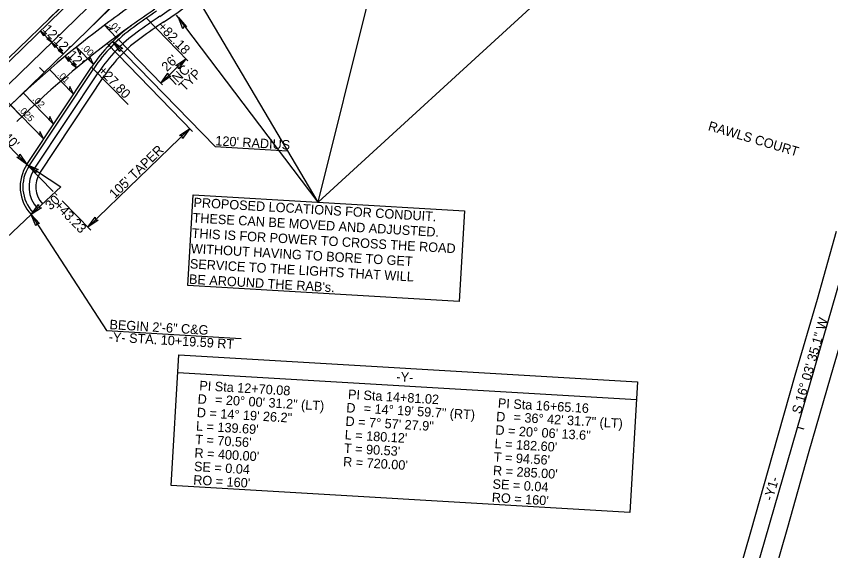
# Model space of a CAD drawing. Extents: x 2010838 to 2015151, y 441905 to 447792.
# Drawn here: x 2011692 to 2012294, y 444289 to 444685 of the extents above; entities that cross this region are included whole.
import ezdxf

# ---------------------------------------------------------------- set-up
doc = ezdxf.new("R2010")
doc.units = 0
for name, color, linetype in [('$AUDIT_BAD_LAYER1', 7, 'Continuous'), ('A-Wall-Blow', 7, 'Continuous'), ('A-Wall-Comp', 7, 'Continuous'), ('C-Building', 7, 'Continuous'), ('C-Grave Plots', 7, 'Continuous'), ('CLRD', 7, 'Continuous'), ('Cont-2-Lidar', 7, 'Continuous'), ('Default_2FT_LIDAR_Contour', 7, 'Continuous'), ('Default_Parcels', 7, 'Continuous'), ('HATCH', 7, 'Continuous'), ('s-Existing Major', 7, 'Continuous'), ('S-Existing Minor', 7, 'Continuous'), ('S-overhead electric', 7, 'Continuous'), ('TEXT-LG', 7, 'Continuous'), ('TEXT-MED', 7, 'Continuous'), ('X2', 7, 'Continuous')]:
    doc.layers.add(name, color=color, linetype=linetype)

msp = doc.modelspace()

# ---------------------------------------------------------------- linework, layer by layer
at = {"layer": '$AUDIT_BAD_LAYER1'}
msp.add_line((2012370.93, 444732.79), (2012193.35, 444115.92), dxfattribs=at)
at = {"layer": 'A-Wall-Blow'}
for p, q in [((2011756.93, 444678.31), (2011765.89, 444669.09)), ((2011736.32, 444662.22), (2011748.79, 444649.38)), ((2011716.32, 444645.49), (2011734.06, 444627.23)), ((2011670.73, 444636.45), (2011712, 444593.97)), ((2011696.78, 444628.3), (2011719.35, 444605.06)), ((2011687.45, 444619.24), (2011695.83, 444610.62))]:
    msp.add_line(p, q, dxfattribs=at)
at = {"layer": 'A-Wall-Comp'}
for points in [[(2011756.93, 444678.31), (2011762.55, 444675.4), (2011760.16, 444675)], [(2011736.32, 444662.22), (2011739.06, 444656.52), (2011739.54, 444658.9)], [(2011748.79, 444649.38), (2011746.04, 444655.08), (2011745.56, 444652.7)], [(2011734.06, 444627.23), (2011731.31, 444632.93), (2011730.84, 444630.55)], [(2011719.35, 444605.06), (2011716.61, 444610.75), (2011716.13, 444608.37)], [(2011712, 444593.97), (2011709.25, 444599.67), (2011708.77, 444597.29)]]:
    msp.add_lwpolyline(points, close=True, dxfattribs=at)
at = {"layer": 'C-Building'}
for p, q in [((2011712.43, 444643.5), (2011708.94, 444647.09)), ((2012269.58, 444380.73), (2012274.38, 444379.35))]:
    msp.add_line(p, q, dxfattribs=at)
at = {"layer": 'CLRD'}
for p, q in [((2012370.93, 444732.79), (2012193.35, 444115.92)), ((2011353.78, 444295.11), (2011783.81, 444712.84))]:
    msp.add_line(p, q, dxfattribs=at)
at = {"layer": 'Default_Parcels'}
msp.add_line((2011811.22, 444421.15), (2012150.63, 444401.14), dxfattribs=at)
msp.add_lwpolyline([(2011811.99, 444434.1), (2012151.4, 444414.1), (2012145.7, 444317.47), (2011806.29, 444337.48)], close=True, dxfattribs=at)
at = {"layer": 'HATCH'}
msp.add_line((2011772.09, 444718.19), (2011632.34, 444582.43), dxfattribs=at)
msp.add_arc((2012222.81, 444060.23), 762, 125.84212, 134.15261, dxfattribs=at)
at = {"layer": 's-Existing Major'}
for points in [[(2011814.82, 444675.57), (2011811.68, 444684.14), (2011817.57, 444677.1), (2011815.61, 444677.3)], [(2011712.2, 444670.46), (2011709.62, 444674.23), (2011713.34, 444671.54), (2011712.37, 444671.4)], [(2011715.4, 444669.39), (2011717.98, 444665.62), (2011714.25, 444668.31), (2011715.23, 444668.45)], [(2011720.56, 444661.85), (2011717.98, 444665.62), (2011721.71, 444662.93), (2011720.73, 444662.79)], [(2011768.26, 444658.88), (2011763.1, 444666.42), (2011770.55, 444661.04), (2011768.6, 444660.75)], [(2011723.76, 444660.78), (2011726.34, 444657.01), (2011722.61, 444659.7), (2011723.59, 444659.85)], [(2011730.53, 444651.59), (2011727.95, 444655.36), (2011731.67, 444652.67), (2011730.7, 444652.53)], [(2011733.73, 444650.52), (2011736.31, 444646.75), (2011732.58, 444649.44), (2011733.56, 444649.59)], [(2011809.68, 444648.41), (2011817.22, 444653.57), (2011811.84, 444646.12), (2011811.55, 444648.07)], [(2011806.05, 444640.69), (2011798.57, 444635.45), (2011803.86, 444642.96), (2011804.17, 444641.02)], [(2011812.51, 444596.78), (2011820.04, 444601.94), (2011814.67, 444594.48), (2011814.38, 444596.43)], [(2011694.42, 444582.79), (2011699.58, 444575.25), (2011692.13, 444580.63), (2011694.07, 444580.92)], [(2011706.21, 444568.97), (2011699.57, 444575.24), (2011707.99, 444571.57), (2011706.15, 444570.87)], [(2011710.32, 444543.15), (2011702.69, 444538.12), (2011708.2, 444545.48), (2011708.45, 444543.53)], [(2011706.28, 444529.73), (2011702.69, 444538.12), (2011708.96, 444531.4), (2011706.99, 444531.49)], [(2011752.26, 444533.94), (2011744.73, 444528.78), (2011750.1, 444536.23), (2011750.39, 444534.28)]]:
    msp.add_lwpolyline(points, close=True, dxfattribs=at)
at = {"layer": 'S-Existing Minor'}
for p, q in [((2011915.11, 444547.35), (2012067.43, 445160.54)), ((2011915.11, 444547.35), (2011665.38, 444969.67)), ((2011915.11, 444547.35), (2012331.51, 444929.43)), ((2011915.11, 444547.35), (2011810.36, 444685.84)), ((2011788.05, 444683.59), (2011818.69, 444652.05)), ((2011709.62, 444674.23), (2011726.34, 444657.01)), ((2011766.77, 444668.19), (2011799.86, 444634.12)), ((2011758.98, 444664.8), (2011822.18, 444599.74)), ((2011763.1, 444666.42), (2011838.76, 444588.53)), ((2011736.33, 444646.73), (2011727.95, 444655.36)), ((2011798.57, 444635.45), (2011817.22, 444653.57)), ((2011747.43, 444647.38), (2011774.41, 444619.59)), ((2011671.71, 444603.94), (2011699.58, 444575.25)), ((2011744.73, 444528.78), (2011820.04, 444601.94)), ((2011838.76, 444588.53), (2011892.29, 444585.38)), ((2011699.57, 444575.24), (2011724.57, 444558.65)), ((2011699.58, 444575.25), (2011719.11, 444555.15)), ((2011702.69, 444538.12), (2011724.57, 444558.65)), ((2011725.75, 444548.31), (2011746.86, 444526.58)), ((2011702.69, 444538.12), (2011758.35, 444452.21)), ((2011758.35, 444452.21), (2011858.18, 444446.32))]:
    msp.add_line(p, q, dxfattribs=at)
msp.add_lwpolyline([(2011822.62, 444552.8), (2012023.4, 444540.96), (2012019.43, 444473.76), (2011818.65, 444485.59)], close=True, dxfattribs=at)
at = {"layer": 'S-overhead electric'}
for p, q in [((2011623.98, 444591.04), (2011755.87, 444719.16)), ((2011699.57, 444575.24), (2011747.43, 444647.38)), ((2011702.69, 444538.12), (2011684.45, 444521))]:
    msp.add_line(p, q, dxfattribs=at)
for points in [[(2012214.85, 444140.57), (2012231.36, 444197.54), (2012246.95, 444252.5), (2012262.48, 444306.6), (2012277.82, 444361.05), (2012294.5, 444419.12), (2012308.07, 444465.48), (2012323.92, 444521.61), (2012337.25, 444572.21), (2012352.19, 444622.1), (2012368.35, 444674.41)], [(2012298.31, 444525.62), (2012284.21, 444475.17), (2012267.75, 444418.87), (2012251.33, 444361.5), (2012234.87, 444302.97), (2012222.75, 444260.78), (2012211.14, 444219.75), (2012193.27, 444158.36)]]:
    msp.add_lwpolyline(points, dxfattribs=at)
for centre, radius, start, end in [((2011328.64, 445107.17), 600, 314.56735, 343.62875), ((2012222.81, 444060.23), 774, 124.04743, 127.31977), ((2012222.81, 444060.23), 762, 124.2188, 125.78328), ((2011328.64, 445107.17), 600, 314.16903, 314.56735), ((2012222.81, 444060.23), 774, 127.31977, 134.16903), ((2011847.42, 444581.04), 120, 125.78328, 146.4397), ((2011724.57, 444558.65), 30, 146.4397, 223.18139)]:
    msp.add_arc(centre, radius, start, end, dxfattribs=at)
at = {"layer": 'TEXT-LG'}
for p, q in [((2011704.98, 444571.64), (2011752.84, 444643.78)), ((2011709.15, 444568.88), (2011757.01, 444641.02))]:
    msp.add_line(p, q, dxfattribs=at)
for centre, radius, start, end in [((2011629.97, 444941.31), 306.5, 303.21306, 341.32797), ((2011629.97, 444941.31), 311.5, 303.21306, 341.32797), ((2012222.81, 444060.23), 755.5, 124.2188, 125.78328), ((2012222.81, 444060.23), 750.5, 124.2188, 125.78328), ((2011847.42, 444581.04), 113.5, 125.78328, 146.4397), ((2011847.42, 444581.04), 108.5, 125.78328, 146.4397), ((2011724.57, 444558.65), 23.5, 146.4397, 223.18139), ((2011724.57, 444558.65), 18.5, 146.4397, 223.18139)]:
    msp.add_arc(centre, radius, start, end, dxfattribs=at)
at = {"layer": 'TEXT-MED'}
for p, q in [((2011651.27, 444620.34), (2011754.48, 444720.6)), ((2011701.23, 444574.13), (2011749.09, 444646.27))]:
    msp.add_line(p, q, dxfattribs=at)
for centre, radius, start, end in [((2012222.81, 444060.23), 760, 124.2188, 125.78328), ((2011847.42, 444581.04), 118, 125.78328, 146.4397), ((2011724.57, 444558.65), 28, 146.4397, 223.18139)]:
    msp.add_arc(centre, radius, start, end, dxfattribs=at)
at = {"layer": 'X2'}
for p, q in [((2011715.81, 444683.04), (2011730.15, 444696.97)), ((2011678.66, 444646.95), (2011693, 444660.88))]:
    msp.add_line(p, q, dxfattribs=at)

# ---------------------------------------------------------------- texts
at = {"layer": 'A-Wall-Blow'}
for s, p in [('.01', (2011759.99, 444678.67)), ('.00', (2011739.48, 444661.69)), ('.01', (2011721.66, 444641.45)), ('.02', (2011703.31, 444623.23)), ('.025', (2011692.83, 444615.74))]:
    msp.add_text(s, height=5, rotation=314.16903, dxfattribs=at).set_placement(p)
at = {"layer": 'C-Grave Plots'}
for s, rotation, p in [("12'", 314.16903, (2011710.68, 444674.92)), ('+82.18', 314.16436, (2011795.86, 444676.86)), ("12'", 314.16903, (2011718.94, 444666.24)), ("12'", 314.16903, (2011729.12, 444655.67)), ("26'", 44.07451, (2011803.2, 444643.62)), ('+27.80', 314.16436, (2011751.78, 444644.17)), ('INC. ', 44.07451, (2011809.14, 444633.54)), ('TYP', 44.07451, (2011816.05, 444628.95)), ('RAWLS COURT', 343.5592, (2012203.02, 444600.72)), ("40'", 314.15261, (2011681.16, 444595.04)), ("120' RADIUS", 356.62643, (2011838.84, 444589.42)), ("105' TAPER", 44.16903, (2011764.59, 444549.56)), ("30'", 43.18139, (2011717.01, 444541.02)), ('+43.23', 314.16436, (2011719.15, 444544.39))]:
    msp.add_text(s, height=7, rotation=rotation, dxfattribs=at).set_placement(p)
at = {"layer": 'Cont-2-Lidar'}
msp.add_text('S 16%%d 03\' 35.1" W', height=7, rotation=73.94025, dxfattribs=at).set_placement((2012272.05, 444390.05))
at = {"layer": 'Default_2FT_LIDAR_Contour'}
msp.add_text('-Y1-', height=7, rotation=73.94025, dxfattribs=at).set_placement((2012251.22, 444325.71))
at = {"layer": 'Default_Parcels'}
for s, rotation, p in [('-Y-', 356.62643, (2011972.79, 444414.67)), ('PI Sta 12+70.08', 356.62609, (2011826.97, 444408.08)), ('PI Sta 14+81.02', 356.62609, (2011936.97, 444401.59)), ('D', 356.62609, (2011825.71, 444398.13)), ('= 20%%d 00\' 31.2" (LT)', 356.62609, (2011838.56, 444397.67)), ('D', 356.62609, (2011935.71, 444391.65)), ('= 14%%d 19\' 59.7" (RT)', 356.62609, (2011948.56, 444391.19)), ('PI Sta 16+65.16', 356.62609, (2012047.85, 444395.06)), ('D = 14%%d 19\' 26.2"', 356.62609, (2011825.12, 444388.15)), ('D', 356.62609, (2012046.59, 444385.11)), ('= 36%%d 42\' 31.7" (LT)', 356.62609, (2012059.43, 444384.65)), ("L = 139.69'", 356.62609, (2011824.53, 444378.17)), ('D = 7%%d 57\' 27.9"', 356.62609, (2011935.12, 444381.67)), ("L = 180.12'", 356.62609, (2011934.54, 444371.68)), ('D = 20%%d 06\' 13.6"', 356.62609, (2012046, 444375.13)), ("T = 70.56'", 356.62609, (2011823.94, 444368.19)), ("T = 90.53'", 356.62609, (2011933.95, 444361.7)), ("L = 182.60'", 356.62609, (2012045.41, 444365.15)), ("R = 400.00'", 356.62609, (2011823.36, 444358.2)), ("T = 94.56'", 356.62609, (2012044.82, 444355.17)), ('SE = 0.04', 356.62643, (2011823.02, 444348.19)), ("R = 720.00'", 356.62609, (2011933.36, 444351.72)), ("R = 285.00'", 356.62609, (2012044.23, 444345.18)), ("RO = 160'", 356.62643, (2011822.47, 444338.21)), ('SE = 0.04', 356.62643, (2012043.89, 444335.17)), ("RO = 160'", 356.62643, (2012043.35, 444325.19))]:
    msp.add_text(s, height=7, rotation=rotation, dxfattribs=at).set_placement(p)
at = {"layer": 'S-Existing Minor'}
for s, p in [('PROPOSED LOCATIONS FOR CONDUIT.', (2011822.67, 444543.7)), ('THESE CAN BE MOVED AND ADJUSTED.', (2011822, 444532.34)), ('THIS IS FOR POWER TO CROSS THE ROAD', (2011821.33, 444520.99)), ('WITHOUT HAVING TO BORE TO GET', (2011820.66, 444509.63)), ('SERVICE TO THE LIGHTS THAT WILL', (2011819.99, 444498.28)), ("BE AROUND THE RAB's.", (2011819.32, 444486.92)), ('BEGIN 2\'-6" C&G', (2011760.52, 444453.29)), ('-Y- STA. 10+19.59 RT', (2011759.98, 444444.13))]:
    msp.add_text(s, height=7, rotation=356.62643, dxfattribs=at).set_placement(p)

doc.saveas('drawing.dxf')
